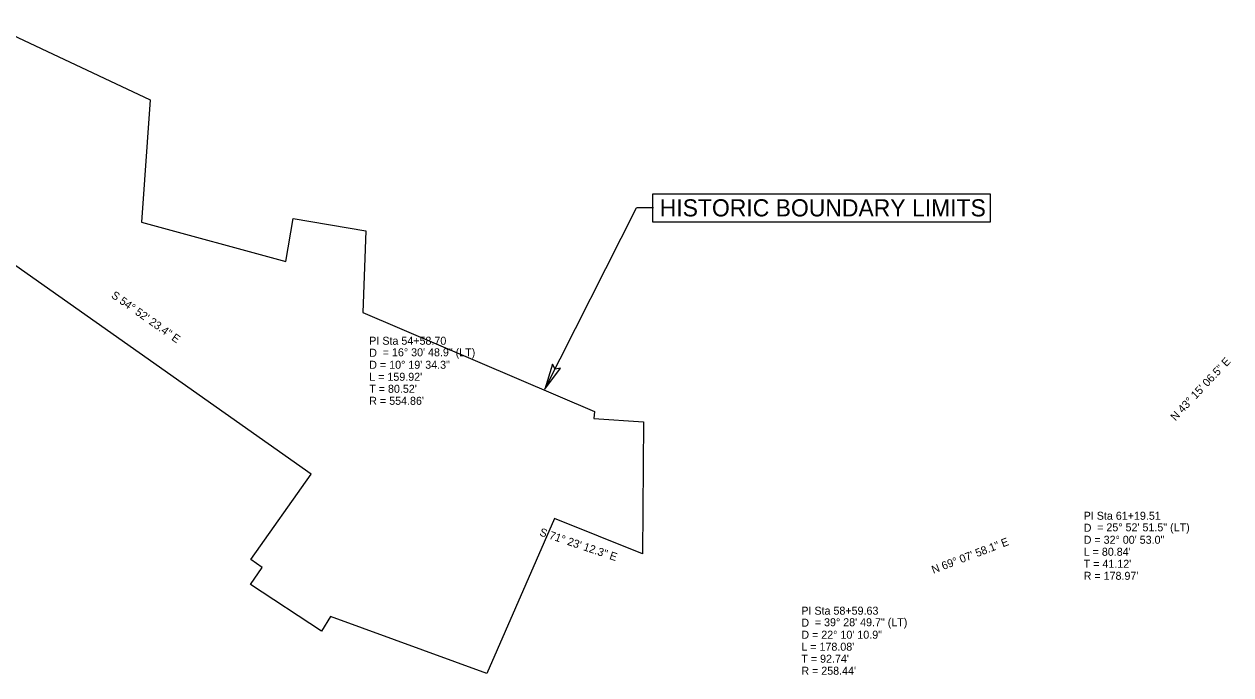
# Model space of a CAD drawing. Extents: x 928111 to 937215, y 684220 to 686530.
# Drawn here: x 931600 to 932656, y 684344 to 684913 of the extents above; entities that cross this region are included whole.
import ezdxf

# ---------------------------------------------------------------- set-up
doc = ezdxf.new("R2010")
doc.units = 0
for name, color, linetype in [('Default', 7, 'Continuous'), ('Exist Boundary Study Area', 7, 'Continuous'), ('Exist Horizontal Alignment Curve and Spiral Data', 7, 'Continuous'), ('Exist Horizontal Alignment Direction Label', 7, 'Continuous'), ('Prop DSN Text', 7, 'Continuous'), ('Prop Terminator CELL', 7, 'Continuous')]:
    doc.layers.add(name, color=color, linetype=linetype)

msp = doc.modelspace()

# ---------------------------------------------------------------- linework, layer by layer
at = {"layer": 'Default'}
for p in [(932055.6, 684594.2), (932150.8, 684752.6)]:
    msp.add_line(p, (932135.8, 684752.6), dxfattribs=at)
at = {"layer": 'Exist Boundary Study Area'}
msp.add_lwpolyline([(931569.5, 684913.3), (931710.3, 684847), (931702.7, 684740.2), (931829.1, 684705.8), (931835.5, 684743.3), (931898.9, 684732.5), (931896.5, 684661.1), (932099.1, 684574.6), (932098.6, 684568.5), (932142, 684565.5), (932141, 684450.3), (932064.1, 684481.2), (932004.9, 684345.6), (931868, 684395.4), (931860.2, 684382.6), (931798.1, 684423.5), (931808.3, 684438.3), (931798.3, 684445.3), (931851.3, 684519.9), (931442, 684808)], dxfattribs=at)
at = {"layer": 'Prop DSN Text'}
msp.add_lwpolyline([(932149.9, 684740.5), (932445.5, 684740.5), (932445.5, 684764.6), (932149.9, 684764.6)], close=True, dxfattribs=at)
at = {"layer": 'Prop Terminator CELL'}
msp.add_lwpolyline([(932062.3, 684616.1), (932055.6, 684594.2), (932069.4, 684612.6), (932064.5, 684611.8)], close=True, dxfattribs=at)

# ---------------------------------------------------------------- texts
at = {"layer": 'Exist Horizontal Alignment Curve and Spiral Data'}
for s, p in [('PI Sta 54+58.70', (931902, 684633)), ('D', (931902, 684622.5)), ('= 16%%d 30\' 48.9" (LT)', (931913.8, 684622.9)), ('D = 10%%d 19\' 34.3"', (931902, 684612)), ("L = 159.92'", (931902, 684601.5)), ("T = 80.52'", (931902, 684591)), ("R = 554.86'", (931902, 684580.5)), ('PI Sta 61+19.51', (932527, 684480)), ('= 25%%d 52\' 51.5" (LT)', (932538.8, 684469.9)), ('D', (932527, 684469.5)), ('D = 32%%d 00\' 53.0"', (932527, 684459)), ("L = 80.84'", (932527, 684448.5)), ("T = 41.12'", (932527, 684438)), ("R = 178.97'", (932527, 684427.5)), ('PI Sta 58+59.63', (932280, 684397)), ('D', (932280, 684386.5)), ('= 39%%d 28\' 49.7" (LT)', (932291.8, 684386.9)), ('D = 22%%d 10\' 10.9"', (932280, 684376)), ("L = 178.08'", (932280, 684365.5)), ("T = 92.74'", (932280, 684355)), ("R = 258.44'", (932280, 684344.5))]:
    msp.add_text(s, height=7, dxfattribs=at).set_placement(p)
at = {"layer": 'Exist Horizontal Alignment Direction Label'}
for s, rotation, p in [('S 54%%d 52\' 23.4" E', 324.8732, (931675.6, 684674.8)), ('N 43%%d 15\' 06.5" E', 46.7482, (932607.2, 684566)), ('S 71%%d 23\' 12.3" E', 341.3867, (932050.4, 684466.4)), ('N 69%%d 07\' 58.1" E', 20.8672, (932395.5, 684432.7))]:
    msp.add_text(s, height=7, rotation=rotation, dxfattribs=at).set_placement(p)
at = {"layer": 'Prop DSN Text'}
msp.add_text('HISTORIC BOUNDARY LIMITS', height=15, dxfattribs=at).set_placement((932156.1, 684745.2))

doc.saveas('drawing.dxf')
